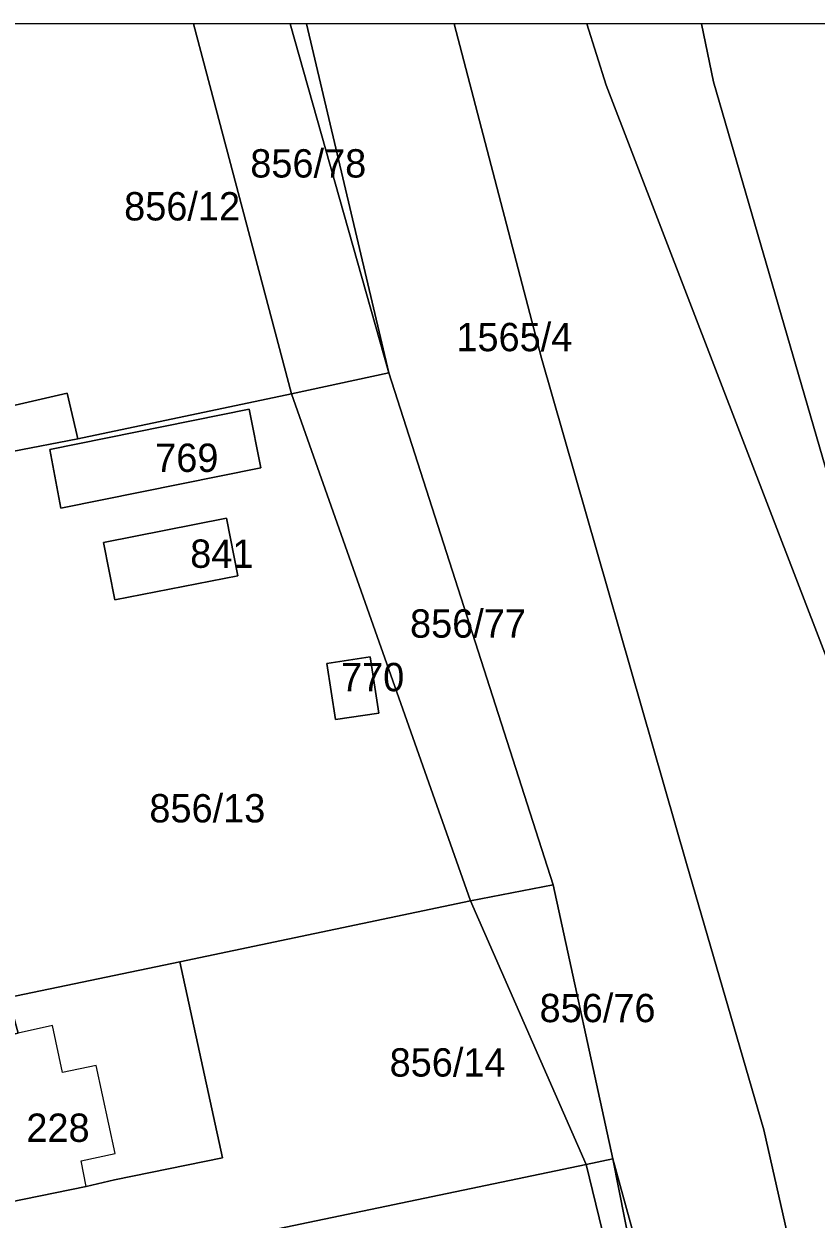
# Model space of a CAD drawing. Extents: x -564940 to -564406, y -1066466 to -1066072.
# Drawn here: x -564537.3 to -564481.4, y -1066156.4 to -1066072 of the extents above; entities that cross this region are included whole.
import ezdxf

# ---------------------------------------------------------------- set-up
doc = ezdxf.new("R2010")
doc.units = 0
for name, color, linetype in [('ft_parcela_polygon', 7, 'Continuous'), ('ft_parcela_text', 7, 'Continuous'), ('ft_stavebni_objekt_polygon', 7, 'Continuous')]:
    doc.layers.add(name, color=color, linetype=linetype)

msp = doc.modelspace()

# ---------------------------------------------------------------- linework, layer by layer
at = {"layer": 'ft_parcela_polygon'}
for p, q in [((-564525.31, -1066072.016), (-564543.042, -1066072.016)), ((-564518.508, -1066072.016), (-564525.31, -1066072.016)), ((-564517.351, -1066072.016), (-564518.508, -1066072.016)), ((-564506.928, -1066072.016), (-564517.351, -1066072.016)), ((-564497.568, -1066072.016), (-564506.928, -1066072.016)), ((-564489.478, -1066072.016), (-564497.568, -1066072.016)), ((-564480.293, -1066072.016), (-564489.478, -1066072.016))]:
    msp.add_line(p, q, dxfattribs=at)
for points in [[(-564506.928, -1066072.016), (-564500.76, -1066095.62), (-564490.54, -1066131.29), (-564485.08, -1066150.07), (-564474.86, -1066195.24), (-564468.44, -1066228.77), (-564474.86, -1066248.97), (-564479.58, -1066256.49), (-564510.51, -1066292.89), (-564526.05, -1066309.43), (-564540.77, -1066329.78), (-564548.05, -1066345), (-564588.23, -1066424.58), (-564607.75, -1066462.97), (-564609.274, -1066465.633)], [(-564609.274, -1066465.633), (-564607.75, -1066462.97), (-564588.23, -1066424.58), (-564548.05, -1066345), (-564540.77, -1066329.78), (-564526.05, -1066309.43), (-564510.51, -1066292.89), (-564479.58, -1066256.49), (-564474.86, -1066248.97), (-564468.44, -1066228.77), (-564474.86, -1066195.24), (-564485.08, -1066150.07), (-564490.54, -1066131.29), (-564500.76, -1066095.62), (-564506.928, -1066072.016)], [(-564600.773, -1066465.633), (-564576.34, -1066428.17), (-564561.1, -1066399.98), (-564552.57, -1066377.06), (-564544.46, -1066346.76), (-564506.9, -1066296.8), (-564477.41, -1066257.73), (-564467.26, -1066239.44), (-564459.83, -1066220.33), (-564457.63, -1066204.67), (-564458.61, -1066193.4), (-564464.89, -1066162.6), (-564473.06, -1066136.49), (-564496.21, -1066076.34), (-564497.568, -1066072.016)], [(-564497.568, -1066072.016), (-564496.21, -1066076.34), (-564473.06, -1066136.49), (-564464.89, -1066162.6), (-564458.61, -1066193.4), (-564457.63, -1066204.67), (-564459.83, -1066220.33), (-564467.26, -1066239.44), (-564477.41, -1066257.73), (-564506.9, -1066296.8), (-564544.46, -1066346.76), (-564552.57, -1066377.06), (-564561.1, -1066399.98), (-564576.34, -1066428.17), (-564600.773, -1066465.633)], [(-564582.262, -1066465.633), (-564558.38, -1066426.97), (-564543.55, -1066398.93), (-564535.25, -1066353.98), (-564532.13, -1066347.45), (-564528.58, -1066341.81), (-564512.56, -1066319.56), (-564480.38, -1066282.47), (-564462.14, -1066258.44), (-564447.75, -1066227.88), (-564442.56, -1066204.14), (-564443.92, -1066174.88), (-564448.27, -1066160.12), (-564456.43, -1066140.31), (-564460.8, -1066129.7), (-564472.45, -1066131.84), (-564488.63, -1066076.11), (-564489.478, -1066072.016)], [(-564543.042, -1066072.016), (-564542.12, -1066077.62), (-564540.87, -1066087.53), (-564538.81, -1066099.13), (-564534.23, -1066098.07), (-564533.62, -1066100.7), (-564533.47, -1066101.3), (-564518.41, -1066098.12), (-564525.31, -1066072.016)], [(-564517.351, -1066072.016), (-564511.53, -1066096.64), (-564499.95, -1066132.78), (-564495.72, -1066152.13), (-564483.94, -1066194.96), (-564487.13, -1066195.66), (-564489.46, -1066196.17), (-564488.87, -1066201.72), (-564483.47, -1066203.67), (-564477.79, -1066223.35), (-564484.89, -1066252.03), (-564502.6, -1066269.26), (-564519.39, -1066285.88), (-564526.09, -1066292.91)], [(-564525.31, -1066072.016), (-564518.41, -1066098.12), (-564511.53, -1066096.64), (-564518.508, -1066072.016)], [(-564518.508, -1066072.016), (-564511.53, -1066096.64), (-564517.351, -1066072.016)], [(-564489.478, -1066072.016), (-564488.63, -1066076.11), (-564472.45, -1066131.84), (-564460.8, -1066129.7), (-564477.25, -1066081.28), (-564478.79, -1066080.85), (-564478.16, -1066078.59), (-564479.61, -1066074.32), (-564480.293, -1066072.016)]]:
    msp.add_lwpolyline(points, dxfattribs=at)
for points in [[(-564540.33, -1066102.66), (-564538.1, -1066102.2), (-564533.47, -1066101.3), (-564533.62, -1066100.7), (-564534.23, -1066098.07), (-564538.81, -1066099.13), (-564540.87, -1066087.53), (-564560.44, -1066091.42), (-564557.86, -1066106.36)], [(-564518.41, -1066098.12), (-564505.78, -1066133.92), (-564499.95, -1066132.78), (-564511.53, -1066096.64)], [(-564557.86, -1066106.36), (-564550.58, -1066143.31), (-564538.37, -1066140.75), (-564526.27, -1066138.21), (-564505.78, -1066133.92), (-564518.41, -1066098.12), (-564533.47, -1066101.3), (-564538.1, -1066102.2), (-564540.33, -1066102.66)], [(-564520.56, -1066103.34), (-564521.39, -1066099.22), (-564535.46, -1066102.06), (-564534.68, -1066106.2)], [(-564521.39, -1066099.22), (-564520.56, -1066103.34), (-564534.68, -1066106.2), (-564535.46, -1066102.06)], [(-564522.98, -1066106.91), (-564522.18, -1066110.97), (-564530.86, -1066112.68), (-564531.66, -1066108.62)], [(-564530.86, -1066112.68), (-564522.18, -1066110.97), (-564522.98, -1066106.91), (-564531.66, -1066108.62)], [(-564512.85, -1066116.7), (-564512.23, -1066120.66), (-564515.3, -1066121.12), (-564515.9, -1066117.16)], [(-564515.3, -1066121.12), (-564512.23, -1066120.66), (-564512.85, -1066116.7), (-564515.9, -1066117.16)], [(-564497.61, -1066152.52), (-564495.72, -1066152.13), (-564499.95, -1066132.78), (-564505.78, -1066133.92)], [(-564550.58, -1066143.31), (-564546.4, -1066162.66), (-564522.08, -1066157.63), (-564497.61, -1066152.52), (-564505.78, -1066133.92), (-564526.27, -1066138.21), (-564523.28, -1066152.05), (-564530.88, -1066153.6), (-564532.9, -1066154.07), (-564542.69, -1066156.09), (-564544.87, -1066146.53), (-564540.76, -1066145.68), (-564541.1, -1066144.02), (-564537.69, -1066143.25), (-564538.37, -1066140.75)], [(-564538.37, -1066140.75), (-564537.69, -1066143.25), (-564541.1, -1066144.02), (-564540.76, -1066145.68), (-564544.87, -1066146.53), (-564542.69, -1066156.09), (-564532.9, -1066154.07), (-564530.88, -1066153.6), (-564523.28, -1066152.05), (-564526.27, -1066138.21)], [(-564492.82, -1066194.92), (-564491.97, -1066194.96), (-564492.48, -1066177.99), (-564494.44, -1066165.57), (-564497.61, -1066152.52), (-564522.08, -1066157.63), (-564518.81, -1066173.98), (-564516.88, -1066193.76), (-564500.54, -1066194.55), (-564502.52, -1066180.79), (-564511.52, -1066182.05), (-564512.8, -1066172.95), (-564503.79, -1066171.68), (-564502.33, -1066171.19), (-564502.7, -1066168.64), (-564496.72, -1066167.78), (-564496.36, -1066170.33)], [(-564491.97, -1066194.96), (-564487.13, -1066195.66), (-564495.72, -1066152.13), (-564497.61, -1066152.52), (-564494.44, -1066165.57), (-564492.48, -1066177.99)], [(-564487.13, -1066195.66), (-564483.94, -1066194.96), (-564495.72, -1066152.13)]]:
    msp.add_lwpolyline(points, close=True, dxfattribs=at)
at = {"layer": 'ft_stavebni_objekt_polygon'}
msp.add_lwpolyline([(-564540.76, -1066145.68), (-564544.87, -1066146.53), (-564542.69, -1066156.09), (-564532.9, -1066154.07), (-564533.25, -1066152.26), (-564530.85, -1066151.74), (-564532.18, -1066145.53), (-564534.56, -1066146.03), (-564535.27, -1066142.71), (-564537.69, -1066143.25), (-564541.1, -1066144.02)], close=True, dxfattribs=at)

# ---------------------------------------------------------------- texts
at = {"layer": 'ft_parcela_text'}
for s, p in [('856/78', (-564521.31, -1066082.86)), ('856/12', (-564530.21, -1066085.89)), ('1565/4', (-564506.77, -1066095.12)), ('769', (-564528.02, -1066103.64)), ('841', (-564525.55, -1066110.41)), ('856/77', (-564510.04, -1066115.34)), ('770', (-564514.91, -1066119.12)), ('856/13', (-564528.43, -1066128.38)), ('856/76', (-564500.9, -1066142.48)), ('856/14', (-564511.48, -1066146.32)), ('228', (-564537.11, -1066150.93))]:
    msp.add_text(s, height=2, dxfattribs=at).set_placement(p)

doc.saveas('drawing.dxf')
